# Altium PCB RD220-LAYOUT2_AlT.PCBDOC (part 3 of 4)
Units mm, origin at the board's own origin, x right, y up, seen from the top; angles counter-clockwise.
Board outline 250 x 145 mm, 4 copper layers (TOP, Mid-Layer 1, Mid-Layer 2, BOTTOM), stack 0.711 mm thick; 497 components, 207 nets, 1178 pads, 436 vias.
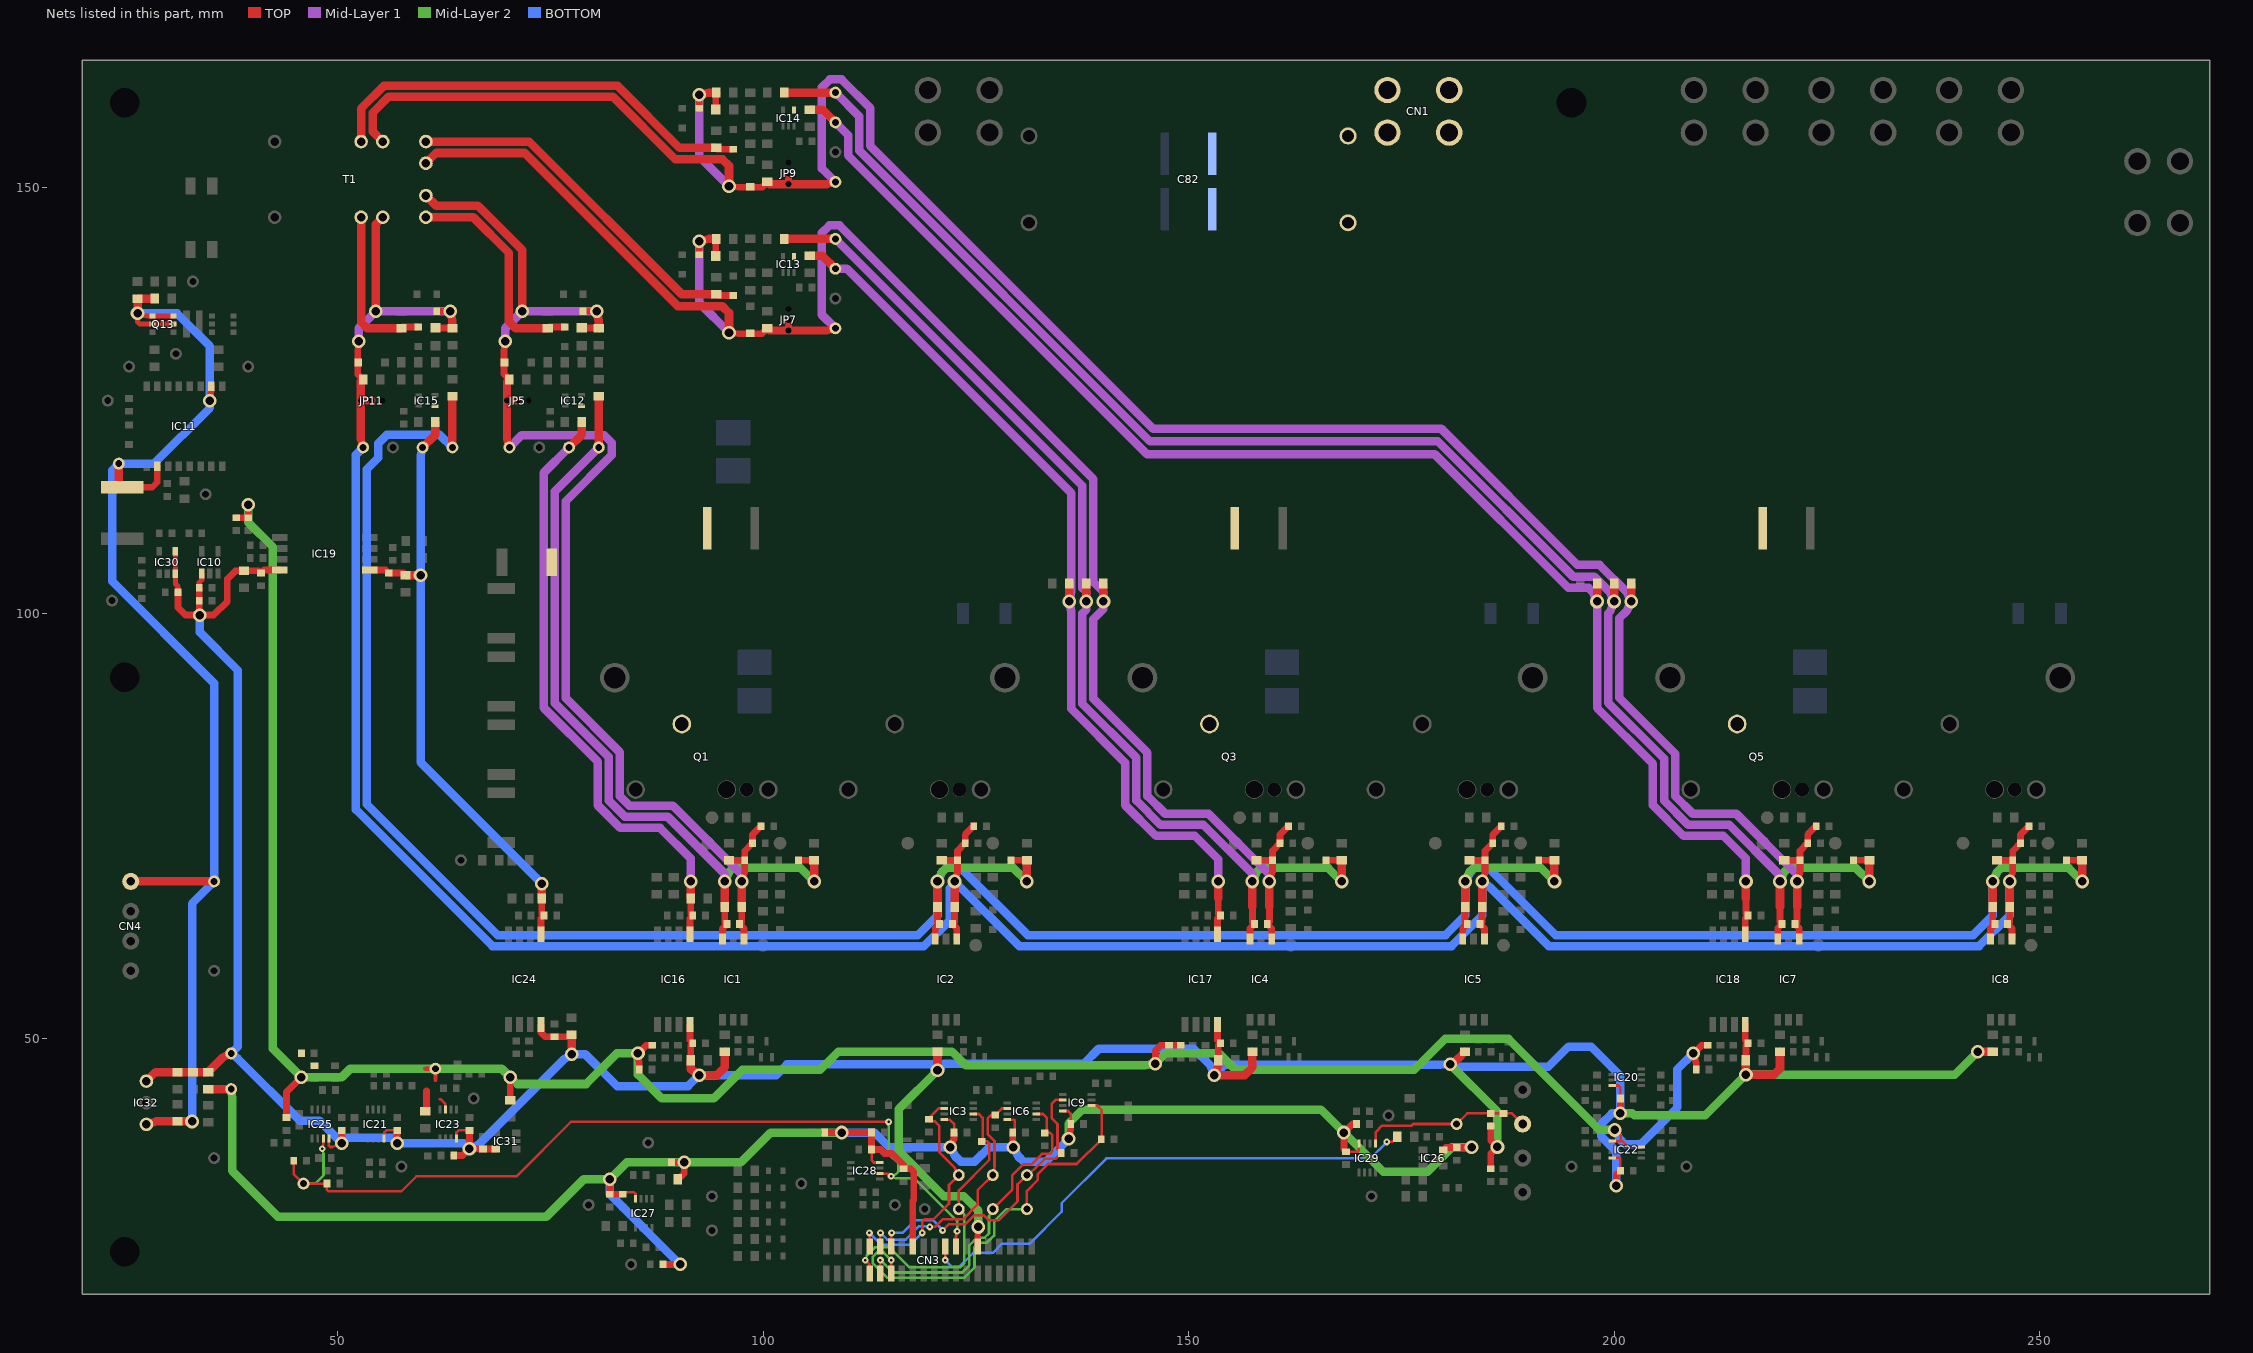
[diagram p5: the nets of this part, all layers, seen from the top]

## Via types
v1: diameter 1.6, hole 1, TOP to BOTTOM, 364 vias
v2: diameter 0.8, hole 0.3, TOP to BOTTOM, 68 vias
v3: diameter 8, hole 3.5, TOP to BOTTOM, 4 vias

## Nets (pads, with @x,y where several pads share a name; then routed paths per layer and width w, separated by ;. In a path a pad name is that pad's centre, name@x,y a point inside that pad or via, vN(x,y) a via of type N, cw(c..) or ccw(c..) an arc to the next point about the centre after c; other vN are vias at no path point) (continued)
T1_B: C68.1 D29.A T1.2 | length 19.4
  TOP w0.8: C68.1@57.5,133.5 57.65,133.65 D29.A@59.5,133.65
  TOP w1: T1.2@52.77,146.555 52.77,134.23 53.5,133.5 C68.1@57.5,133.5
T1_U: C47.1 D16.A T1.4 | length 26.5
  TOP w0.8: C47.1@74.7,133.5 74.85,133.65 D16.A@76.7,133.65
  TOP w1: T1.4@60.4,146.555 65.945,146.555 70.1,142.4 70.1,134.35 70.95,133.5 C47.1@74.7,133.5
T1_V: C54.1 D21.A T1.7 | length 43.6
  TOP w0.8: C54.1@94.5,137.5 94.65,137.35 D21.A@96.5,137.35
  TOP w1: T1.7@60.39,155.445 72.505,155.445 90.45,137.5 C54.1@94.5,137.5
T1_W: C61.1 D25.A T1.9 | length 51.8
  TOP w0.8: C61.1@94.5,154.7 94.65,154.55 D25.A@96.5,154.55
  TOP w1: T1.9@52.77,155.45 52.77,159.32 55.45,162 82.9,162 90.2,154.7 C61.1@94.5,154.7
T_RES: C117.2 IC29.5 J3.1 R117.2 TP60.1 | length 20
  TOP w0.3: IC29.5@171.975,37.7 171.975,39.025 172.75,39.8 176.2,39.8 176.4,40 TP60.1@181.5,40 182.75,41.25 R117.2@185.5,41.25 C117.2@187,41.25 188,41.25 J3.1@189.25,40
THM1: CN3.24 R116.2 | length 61.9
  TOP w0.3: v2(121.405,24.006) CN3.24@121.405,25.531 ; v2(173.3,37.9) 173.9,37.9 R116.2@174.5,38.5
  BOTTOM w0.3: v2(121.405,24.006) 122.211,23.2 123.05,23.2 124.7,24.85 127,24.85 128.1,25.95 131.35,25.95 135.1,29.7 135.1,30.7 140.35,35.95 171.35,35.95 v2(173.3,37.9)
UH: CN3.9 IC3.2 R162.1 TP62.1 | length 36.3
  TOP w0.3: v2(112,24) 112.515,23.485 CN3.9@112.515,22.481 ; TP62.1@123,30 123,32.2 126.6,35.8 126.6,37.7 126.35,37.95 R162.1@125.7,37.95 125.8,38.05 125.8,40.725 125.35,41.175 IC3.2@124.7,41.175
  Mid-Layer 2 w0.3: v2(112,24) 112.211,24.561 113.15,25.5 114.85,25.5 117.2,23.15 123.15,23.15 123.65,23.65 123.65,29.35 TP62.1@123,30
UL: CN3.10 IC3.6 R163.1 TP65.1 | length 28.9
  TOP w0.3: v2(112.5,27.2) 112.515,26.675 CN3.10@112.515,25.601 CN3.10@112.515,25.531 ; v2(118.7,27.2) 118.7,28.5 119,28.8 120,28.8 121.85,30.65 121.85,32.85 TP65.1@123,34 122.475,34.91 120.7,36.685 120.7,39.8 120.2,40.3 119.5,40.3 R163.1@119.5,40.55 119.5,40.7 120.625,41.825 IC3.6@121.3,41.825
  BOTTOM w0.3: v2(112.5,27.2) 113.9,25.8 117.3,25.8 v2(118.7,27.2)
VDC: C164.2 CN3.26 IC25.7 IC28.6 R157.1 TP56.1 | length 105
  TOP w0.3: C164.2@44.85,35.7 44.85,34.15 TP56.1@46,33 R157.1@48.75,33 48.75,32.275 48.925,32.1 57.5,32.1 59.25,33.85 71.004,33.85 77.404,40.25 v2(114.75,40.25) ; v2(48.2,37.1) 48.325,37.61 IC25.7@48.325,38.3 ; IC28.6@113.7,34.175 114.725,34.175 v2(115.05,33.85) ; CN3.26@122.675,25.531 CN3.26@122.675,25.601 122.675,26.89 v2(122.8,27.4)
  Mid-Layer 2 w0.3: TP56.1@46,33 47.4,33 48.35,33.95 48.35,36.519 v2(48.2,37.1) ; v2(114.75,40.25) 114.75,36.5 115.9,35.35 115.9,34.4 115.597,34.097 v2(115.05,33.85) 115.595,33.6 117.804,33.6 122.8,28.604 v2(122.8,27.4)
VDD5_A: C39.2 C78.2 C79.2 C98.2 C99.2 C103.2 C104.2 C108.2 C109.2 C113.2 C114.2 C119.2 C120.2 C121.2 C122.2 C123.2 C128.2 C148.2 C150.2 CN3.30 IC10.1 IC16.8 IC17.8 IC18.8 IC19.8 IC20.8 IC21.8 IC22.8 IC23.8 IC24.8 IC25.8 IC30.3 IC30.4 IC31.5 IC32.3 R13.2 R16.2 R30.2 R33.2 R38.2 R41.2 R46.2 R111.1 R117.1 R121.1 R186.1 R187.2 TP70.1 | length 457.3
  TOP w0.3: IC25.8@48.975,38.3 48.975,37.475 49.15,37.3 49.388,37.3 v1(50.5,37.75) ; IC21.8@55.475,38.3 55.475,38.975 55.75,39.25 C122.2@57,39.25 ; IC23.8@63.975,38.3 63.975,39 64.225,39.25 C123.2@65.5,39.25 ; IC22.8@199.8,36.025 200.65,36.025 200.75,35.925 C121.2@200.75,34.5 ; IC20.8@199.8,44.525 200.525,44.525 200.75,44.3 C120.2@200.75,43
  TOP w0.6: IC30.4@30.95,107.315 IC30.3@30.95,104.685 30.95,103.45 31.25,103.15 C128.2@31.25,102.5 ; C39.2@33.75,103 33.75,103.65 34.05,103.95 IC10.1@34.05,104.69
  TOP w0.7: CN3.30@125.215,25.531 CN3.30@125.215,25.601 125.215,26.727 125.315,27.899 v1@125.315,27.9
  TOP w0.8: C128.2@31.25,102.5 31.25,100.7 32.15,99.8 v1(33.8,99.8) ; C39.2@33.75,103 R46.2@33.75,101.5 33.75,100.999 v1(33.8,99.8) ; IC19.8@43.2,105.095 41.345,105.095 C99.2@41,104.75 40.75,105 C98.2@39,105 38,105 37.05,104.05 37.05,101.4 35.45,99.8 v1(33.8,99.8) ; v1(50.5,37.75) C119.2@50.5,39.25 ; v1(57,37.75) C122.2@57,39.25 ; R121.1@63.65,36.3 64.7,36.3 v1(65.5,37.1) ; C123.2@65.5,39.25 v1(65.5,37.1) ; IC31.5@68.6,37.05 C148.2@67.1,37.05 66.699,37.05 v1(65.5,37.1) ; IC24.8@73.905,51.7 73.905,50.77 74.425,50.25 C79.2@75.5,50.25 77.25,50.25 C78.2@77.5,50.5 ; IC16.8@91.405,51.7 91.405,49.845 C104.2@91.75,49.5 91.5,49.25 C103.2@91.5,47.5 ; IC17.8@153.405,51.7 153.405,49.845 C109.2@153.75,49.5 153.5,49.25 C108.2@153.5,47.5 ; R111.1@185.5,34.75 185.5,36.5 v1(186.3,37.3) 185.5,38.1 R117.1@185.5,39.75 ; v1(200.25,32.75) 200.25,34 C121.2@200.75,34.5 ; v1(200.75,41.25) C120.2@200.75,43 ; IC18.8@215.405,51.7 215.405,49.845 C114.2@215.75,49.5 215.5,49.25 C113.2@215.5,47.5
  TOP w1: IC32.3@27.55,45.04 28.61,46.1 C150.2@31.2,46.1 R186.1@33,46.1 R187.2@34.8,46.1 36.551,47.851 TP70.1@37.5,48.3 ; v1@77.5,48 v1(77.5,48.2) C78.2@77.5,50.5 ; C103.2@91.5,47.5 91.5,46.45 91.515,46.435 v1(92.5,45.75) 94.6,45.75 95.5,46.65 R13.2@95.5,48.5 ; v1(120.5,46.3) R16.2@120.5,48.5 ; C108.2@153.5,47.5 153.5,46.841 v1(153,45.75) 156.6,45.75 157.5,46.65 R30.2@157.5,48.5 ; v1(180.75,47) 181.714,47.714 R33.2@182.5,48.5 ; C113.2@215.5,47.5 v1(215.5,45.8) 218.8,45.8 219.5,46.5 R38.2@219.5,48.5 ; v1(242.75,48.5) R41.2@244.5,48.5
  Mid-Layer 2 w1: v1(120.5,46.3) 115.95,41.75 115.95,36.8 121.25,31.5 123.6,31.5 125.3,29.8 v1(125.3,27.9) ; v1(180.75,47) 186.3,41.45 v1(186.3,37.3) ; v1(200.75,41.25) 202.15,41.25 202.4,41 210.7,41 v1(215.5,45.8) 240.05,45.8 v1(242.75,48.5)
  BOTTOM w1: v1(33.8,99.8) 33.8,97.8 38.3,93.3 38.3,49.1 TP70.1@37.5,48.3 38.314,47.636 45.55,40.4 47.85,40.4 v1(50.5,37.75) 51.15,38.4 56.35,38.4 v1(57,37.75) 64.85,37.75 v1(65.5,37.1) 66.594,37.594 76.515,47.515 v1(77.5,48.2) 79.1,48.2 82.85,44.45 91.2,44.45 v1(92.5,45.75) 101.55,45.75 102.8,47 119.8,47 v1(120.5,46.3) 121.3,47.1 137.7,47.1 139.45,48.85 150.6,48.85 152.577,46.873 v1(153,45.75) 154.2,46.95 179.551,46.95 v1(180.75,47) 181.912,46.7 192.25,46.7 194.65,49.1 197.3,49.1 200.75,45.65 v1(200.75,41.25) 199.75,41.25 198.5,40 198.5,38.55 200.25,36.8 v1(200.25,32.75)
VDD5_D: C88.2 C89.2 C90.2 C116.2 C124.2 C125.2 C126.2 CN3.18 IC3.8 IC6.8 IC9.8 IC26.5 IC27.8 IC28.8 IC29.8 R86.1 R88.1 R90.1 R94.1 R95.1 R97.1 R99.1 R100.1 R187.1 TP72.1 | length 247.4
  TOP w0.3: C88.2@83.6,32 84.8,32 85.025,31.775 IC27.8@85.025,31.2 ; C89.2@112.75,37 112.75,35.75 113.025,35.475 IC28.8@113.7,35.475 ; IC3.8@121.3,40.525 121.925,40.525 122.45,40 C124.2@122.45,39 ; IC6.8@128.7,40.525 129.475,40.525 129.6,40.4 129.6,39.25 C125.2@129.35,39 ; IC9.8@135.2,41.525 135.85,41.525 136.15,41.225 C126.2@136.15,40 ; C90.2@168.5,36.75 169.9,36.75 170.025,36.875 IC29.8@170.025,37.7
  TOP w0.8: v1(82,33.5) R99.1@82,31.75 C88.2@83.5,31.75 ; R86.1@88.25,23.5 v1(90.25,23.5) ; R88.1@89.25,35.5 v1(90.75,35.5) 90.75,34.25 R94.1@90,33.5 ; R90.1@107.25,39 v1(109.25,39) R100.1@112.75,39 C89.2@112.75,37 113.8,37 114.25,36.55 115.15,36.55 116.5,35.2 R95.1@116.5,34.75 117.35,34.75 117.7,34.4 117.7,31.05 117.6,30.95 CN3.18@117.6,25.536 ; v1(122,37.25) 122.45,38.362 C124.2@122.45,39 ; C125.2@129.35,39 129.35,38.449 v1(129.4,37.25) ; v1(135.9,38.25) 136.15,39.424 C126.2@136.15,40 ; C90.2@168.5,36.75 168.25,37 v1(168.25,39) 169.25,40 R97.1@169.75,40 ; IC26.5@179.95,36.95 180.25,37.25 C116.2@181.5,37.25 v1(183.25,37.25)
  TOP w1: R187.1@34.8,44.1 TP72.1@37.5,44.1
  Mid-Layer 2 w1: TP72.1@37.5,44.1 37.6,43.13 37.6,34.5 43,29.1 74.525,29.1 78.925,33.5 v1(82,33.5) 84,35.5 v1(90.75,35.5) 97.4,35.5 100.9,39 v1(109.25,39) ; v1(135.9,38.25) 135.9,40.05 137.55,41.7 165.55,41.7 v1(168.25,39) 172.85,34.4 178.1,34.4 180.95,37.25 v1(183.25,37.25)
  BOTTOM w1: v1(82,33.5) 82,31.75 v1(90.25,23.5) ; v1(109.25,39) 113.1,39 114.85,37.25 v1(122,37.25) 122.593,36.207 123.225,35.575 124.875,35.575 126.55,37.25 v1(129.4,37.25) 129.993,36.207 130.65,35.55 133.2,35.55 v1(135.9,38.25)
VDD20_A: C43.2 C44.2 C45.2 C149.2 CN4.1 IC11.2 IC11.10 IC32.1 Q13.1 Q13.2 Q13.5 Q13.6 TP27.1 TP69.1 | length 153.9
  TOP w0.6: Q13.5@30.75,134 Q13.2@28.25,134 26.775,134 26.5,134.275 v1(26.5,135.25) 27.662,134.95 Q13.1@28.25,134.95 Q13.6@30.75,134.95
  TOP w0.75: C43.2@24.7,114.825 24.708,114.817 28.217,114.817 28.825,115.425 IC11.2@28.825,117.301 ; v1(35,125) 35.175,126.187 IC11.10@35.175,126.699
  TOP w1: TP27.1@24.3,117.6 24.3,115.225 C43.2@24.7,114.825 ; CN4.1@25.7,68.5 TP69.1@35.5,68.5 ; v1(26.5,135.25) C44.2@26.5,137 C45.2@28.5,137 ; IC32.1@27.55,39.96 28.701,40.3 C149.2@31.2,40.3 v1(32.9,40.3)
  BOTTOM w1: v1(26.5,135.25) 31.15,135.25 35,131.4 v1(35,125) 35,124.15 28.45,117.6 TP27.1@24.3,117.6 23.5,116.8 23.5,103.8 35.5,91.8 TP69.1@35.5,68.5 32.9,65.9 v1(32.9,40.3)
VH: CN3.11 IC6.2 R170.1 TP63.1 | length 38.2
  TOP w0.3: CN3.11@113.785,22.481 v2(113.785,24.006) ; TP63.1@127,30 129.3,32.3 129.3,34 130.55,35.25 131.525,35.25 132.775,36.5 133.7,36.5 134,36.8 134,38.7 133.75,38.95 R170.1@133.1,38.95 133.35,39.2 133.35,40.7 132.875,41.175 IC6.2@132.1,41.175
  Mid-Layer 2 w0.3: v2(113.785,24.006) 115.241,22.55 123.4,22.55 124.25,23.4 124.25,25.75 125.15,26.65 126.05,26.65 126.55,27.15 126.55,29.135 TP63.1@127,30
VL: CN3.12 IC6.6 R171.1 TP66.1 | length 29.2
  TOP w0.3: CN3.12@113.785,25.531 CN3.12@113.785,25.601 113.785,26.675 v2(113.8,27.2) ; v2(119.6,27.9) 120.2,27.9 121.1,28.8 123.5,28.8 125.215,30.515 125.215,32.215 TP66.1@127,34 127.2,35.031 127.2,38 126.4,38.8 126.4,40.65 126.8,41.05 R171.1@127.3,41.05 128.075,41.825 IC6.6@128.7,41.825
  BOTTOM w0.3: v2(113.8,27.2) 114.6,26.4 116.75,26.4 118.35,28 119.085,28 v2(119.6,27.9)
VN_2V_B: C24.1 C26.1 C30.1 C32.1 C36.1 C38.1 C69.1 C74.1 C130.1 C132.1 C134.1 C138.1 C143.1 C147.1 D4.A D8.A D12.A D28.A DS4.C IC2.4 IC5.4 IC8.4 JP11.1 JP11.2 R26.2 R37.2 R45.2 T1.3 TP44.1 ZD4.A | length 359.6
  TOP w0.8: v1(52.5,132) 52.365,130.808 52.365,128.135 C74.1@53,127.5 ; DS4.C@61.5,133.55 63.45,133.55 C69.1@63.5,133.5 ; D28.A@61.65,135.5 v1(63.25,135.5) ; C26.1@121,71 D4.A@122.85,71 ; C130.1@122.5,65.5 122.5,63.75 C24.1@122.25,63.5 122.77,62.98 IC2.4@122.77,61.75 ; v1(122.5,68.5) 122.85,69.648 D4.A@122.85,71 ; C138.1@124.75,75 123.75,74 R26.2@123.75,73 122.85,72.1 D4.A@122.85,71 ; C32.1@183,71 D8.A@184.85,71 ; C132.1@184.5,65.5 184.5,63.75 C30.1@184.25,63.5 184.77,62.98 IC5.4@184.77,61.75 ; v1(184.5,68.5) 184.85,69.648 D8.A@184.85,71 ; C143.1@186.75,75 185.75,74 R37.2@185.75,73 184.85,72.1 D8.A@184.85,71 ; C38.1@245,71 D12.A@246.85,71 ; C134.1@246.5,65.5 246.5,63.75 C36.1@246.25,63.5 246.77,62.98 IC8.4@246.77,61.75 ; v1(246.5,68.5) 246.85,69.648 D12.A@246.85,71 ; C147.1@248.75,75 247.75,74 R45.2@247.75,73 246.85,72.1 D12.A@246.85,71
  TOP w0.95: TP44.1@53,119.5 52.73,120.515 JP11.1@52.73,125 ; C74.1@53,127.5 52.73,127.23 JP11.1@52.73,125 ; JP11.2@54,125 JP11.1@52.73,125
  TOP w1: v1(54.5,135.5) 54.5,145.745 T1.3@55.31,146.555 ; v1(63.25,135.5) 63.5,134.326 C69.1@63.5,133.5 ; C130.1@122.5,65.5 v1(122.5,68.5) ; C132.1@184.5,65.5 v1(184.5,68.5) ; C134.1@246.5,65.5 v1(246.5,68.5)
  Mid-Layer 1 w1: v1(52.5,132) 52.5,133.5 v1(54.5,135.5) v1(63.25,135.5)
  BOTTOM w1: TP44.1@53,119.5 52.15,118.65 52.15,76.95 68.2,60.9 118.9,60.9 121.95,63.95 121.95,67.7 v1(122.5,68.5) 130.1,60.9 180.9,60.9 184.5,64.5 v1(184.5,68.5) 185.454,67.771 192.325,60.9 242.9,60.9 246.5,64.5 v1(246.5,68.5)
VN_2V_U: C21.1 C23.1 C48.1 C53.1 C129.1 C137.1 D2.A D15.A DS1.C IC1.4 JP5.1 JP5.2 R25.2 T1.5 TP32.1 ZD1.A | length 148.6
  TOP w0.8: v1(69.7,132) 69.565,130.808 69.565,128.135 C53.1@70.2,127.5 ; DS1.C@78.7,133.55 80.65,133.55 C48.1@80.7,133.5 ; D15.A@78.85,135.5 v1(80.45,135.5) ; C23.1@96,71 D2.A@97.85,71 ; C129.1@97.5,65.5 97.5,63.75 C21.1@97.25,63.5 97.77,62.98 IC1.4@97.77,61.75 ; v1(97.5,68.5) 97.85,69.648 D2.A@97.85,71 ; C137.1@99.75,75 98.75,74 R25.2@98.75,73 97.85,72.1 D2.A@97.85,71
  TOP w0.95: TP32.1@70.2,119.5 69.93,120.515 JP5.1@69.93,125 ; C53.1@70.2,127.5 69.93,127.23 JP5.1@69.93,125 ; JP5.2@71.2,125 JP5.1@69.93,125
  TOP w1: T1.5@60.4,149.1 61.6,147.9 66.5,147.9 71.7,142.7 v1(71.7,135.5) ; v1(80.45,135.5) 80.7,134.326 C48.1@80.7,133.5 ; C129.1@97.5,65.5 v1(97.5,68.5)
  Mid-Layer 1 w1: v1(69.7,132) 69.7,133.5 v1(71.7,135.5) v1(80.45,135.5) ; TP32.1@70.2,119.5 71.65,120.95 81.325,120.95 82.2,120.075 82.2,118.575 76.83,113.205 76.83,90.02 83.17,83.68 83.17,78.534 84.304,77.4 89.4,77.4 97.5,69.3 v1(97.5,68.5)
VN_2V_V: C27.1 C29.1 C55.1 C60.1 C131.1 C141.1 D6.A D20.A DS2.C IC4.4 JP7.2 JP7.3 R36.2 T1.6 TP36.1 ZD2.A | length 212.9
  TOP w0.8: D20.A@92.5,142.15 v1(92.5,143.75) ; DS2.C@94.45,142 94.45,143.95 C55.1@94.5,144 ; v1(96,133) 97.192,132.865 99.865,132.865 C60.1@100.5,133.5 ; JP7.3@103,133.23 JP7.2@103,134.5 ; C29.1@158,71 D6.A@159.85,71 ; 159.5,65.5 159.5,63.75 C27.1@159.25,63.5 159.77,62.98 IC4.4@159.77,61.75 ; v1(159.5,68.5) 159.85,69.648 D6.A@159.85,71 ; C141.1@161.75,75 160.75,74 R36.2@160.75,73 159.85,72.1 D6.A@159.85,71
  TOP w0.95: C60.1@100.5,133.5 100.77,133.23 JP7.3@103,133.23 107.485,133.23 TP36.1@108.5,133.5
  TOP w1: T1.6@60.39,152.905 61.585,154.1 72,154.1 90,136.1 95.2,136.1 96,135.3 v1(96,133) ; v1(92.5,143.75) 93.674,144 C55.1@94.5,144 ; v1(140,101.4) C131.1@140,103.5 ; 159.5,65.5 v1(159.5,68.5)
  Mid-Layer 1 w1: v1(92.5,143.75) 92.5,136.5 v1(96,133) ; TP36.1@108.5,133.5 106.9,135.1 106.9,144.7 107.8,145.6 109,145.6 138.83,115.77 138.83,103.67 140,102.5 v1(140,101.4) 140,100.5 138.83,99.33 138.83,89.97 145.17,83.63 145.17,78.534 147.254,76.45 152.35,76.45 159.5,69.3 v1(159.5,68.5)
VN_2V_W: C33.1 C35.1 C62.1 C67.1 C133.1 C145.1 D10.A D24.A DS3.C IC7.4 JP9.2 JP9.3 R44.2 T1.8 TP40.1 ZD3.A | length 283.2
  TOP w0.8: D24.A@92.5,159.35 v1(92.5,160.95) ; DS3.C@94.45,159.2 94.45,161.15 C62.1@94.5,161.2 ; v1(96,150.2) 97.192,150.065 99.865,150.065 C67.1@100.5,150.7 ; JP9.3@103,150.43 JP9.2@103,151.7 ; C35.1@220,71 D10.A@221.85,71 ; 221.5,65.5 221.5,63.75 C33.1@221.25,63.5 221.77,62.98 IC7.4@221.77,61.75 ; v1(221.5,68.5) 221.85,69.648 D10.A@221.85,71 ; C145.1@223.75,75 222.75,74 R44.2@222.75,73 221.85,72.1 D10.A@221.85,71
  TOP w0.95: C67.1@100.5,150.7 100.77,150.43 JP9.3@103,150.43 107.485,150.43 TP40.1@108.5,150.7
  TOP w1: T1.8@55.3,155.45 54.15,156.6 54.15,158.85 56,160.7 82.35,160.7 89.7,153.35 95.25,153.35 96,152.6 v1(96,150.2) ; v1(92.5,160.95) 93.674,161.2 C62.1@94.5,161.2 ; v1(202,101.4) C133.1@202,103.5 ; 221.5,65.5 v1(221.5,68.5)
  Mid-Layer 1 w1: v1(92.5,160.95) 92.5,153.7 v1(96,150.2) ; TP40.1@108.5,150.7 106.925,152.275 106.925,161.825 107.85,162.75 109.225,162.75 112.6,159.375 112.6,154.925 145.825,121.7 179.7,121.7 195.7,105.7 198.3,105.7 201.506,102.494 v1(202,101.4) 201.506,100.306 200.6,99.4 200.6,90.1 207.17,83.53 207.17,78.534 209.254,76.45 214.35,76.45 221.5,69.3 v1(221.5,68.5)
VP_5V_B: C72.2 C76.2 C77.2 C96.2 C97.2 IC15.4 IC19.1 IC24.1 TP42.1 | length 73.2
  TOP w0.8: IC19.1@53.8,105.095 55.655,105.095 C97.2@56,104.75 57.75,104.75 C96.2@58,104.5 ; IC24.1@73.905,62.3 73.905,64.155 C77.2@74.25,64.5 74,64.75 C76.2@74,66.5
  TOP w1: C96.2@58,104.5 v1(59.75,104.5) ; TP42.1@60,119.5 61.5,121 C72.2@61.5,122.5 ; C76.2@74,66.5 v1(74,68.25)
  BOTTOM w1: TP42.1@60,119.5 59.75,118.48 v1(59.75,104.5) 59.75,82.5 v1(74,68.25)
VP_5V_U: C51.2 C101.2 C102.2 IC12.4 IC16.1 TP30.1 | length 72.2
  TOP w0.8: IC16.1@91.405,62.3 91.405,64.155 C102.2@91.75,64.5 91.5,64.75 C101.2@91.5,66.5
  TOP w1: TP30.1@77.2,119.5 78.7,121 C51.2@78.7,122.5 ; C101.2@91.5,66.5 v1(91.5,68.5)
  Mid-Layer 1 w1: TP30.1@77.2,119.5 74.23,116.53 74.23,88.92 80.57,82.58 80.57,77.457 83.227,74.8 87.9,74.8 91.5,71.2 v1(91.5,68.5)
VP_5V_V: C58.2 C106.2 C107.2 IC13.4 IC17.1 TP34.1 | length 106.3
  TOP w0.8: IC17.1@153.405,62.3 153.405,64.155 C107.2@153.75,64.5 153.5,64.75 153.5,66.5
  TOP w1: C58.2@105.5,142 107,142 TP34.1@108.5,140.5 ; v1(136,101.4) C106.2@136,103.5 ; 153.5,66.5 v1(153.5,68.5)
  Mid-Layer 1 w1: TP34.1@108.5,140.5 109.85,140.5 136.23,114.12 136.23,102.578 v1(136,101.4) 136.23,100.222 136.23,88.77 142.57,82.43 142.57,77.457 146.177,73.85 150.75,73.85 153.5,71.1 v1(153.5,68.5)
VP_5V_W: C65.2 C111.2 C112.2 IC14.4 IC18.1 TP38.1 | length 169.5
  TOP w0.8: IC18.1@215.405,62.3 215.405,64.155 C112.2@215.75,64.5 215.5,64.75 215.5,66.5
  TOP w1: C65.2@105.5,159.2 107,159.2 TP38.1@108.5,157.7 ; v1(198,101.4) C111.2@198,103.5 ; 215.5,66.5 v1(215.5,68.5)
  Mid-Layer 1 w1: TP38.1@108.5,157.7 110,156.2 110,153.825 145.125,118.7 178.939,118.7 194.639,103 197,103 197.506,102.494 v1(198,101.4) 198,88.9 204.57,82.33 204.57,77.457 208.177,73.85 212.85,73.85 215.5,71.2 v1(215.5,68.5)
VP_18V_B: C24.2 C25.2 C30.2 C31.2 C36.2 C37.2 C130.2 C132.2 C134.2 D3.C D7.C D11.C IC2.6 IC5.6 IC8.6 R61.2 TP41.1 | length 349.8
  TOP w0.8: IC2.6@120.23,61.75 120.23,62.98 C24.2@120.75,63.5 120.5,63.75 C130.2@120.5,65.5 ; D3.C@129.15,71 C25.2@131,71 ; IC5.6@182.23,61.75 182.23,62.98 C30.2@182.75,63.5 182.5,63.75 C132.2@182.5,65.5 ; D7.C@191.15,71 C31.2@193,71 ; IC8.6@244.23,61.75 244.23,62.98 C36.2@244.75,63.5 244.5,63.75 C134.2@244.5,65.5 ; D11.C@253.15,71 C37.2@255,71
  TOP w1: TP41.1@63.5,119.5 R61.2@63.5,125.5 ; C130.2@120.5,65.5 v1(120.5,68.5) ; v1(131,68.5) C25.2@131,71 ; C132.2@182.5,65.5 v1(182.5,68.5) ; v1(193,68.5) C31.2@193,71 ; C134.2@244.5,65.5 v1(244.5,68.5) ; v1(255,68.5) C37.2@255,71
  Mid-Layer 2 w1: v1(120.5,68.5) 120.994,69.594 121.5,70.1 129.4,70.1 v1(131,68.5) ; v1(182.5,68.5) 182.994,69.594 183.5,70.1 191.4,70.1 v1(193,68.5) ; v1(244.5,68.5) 244.994,69.594 245.5,70.1 253.4,70.1 v1(255,68.5)
  BOTTOM w1: TP41.1@63.5,119.5 62,121 55.8,121 54.8,120 54.8,118.3 53.45,116.95 53.45,77.55 68.8,62.2 118.2,62.2 120.5,64.5 v1(120.5,68.5) 121.028,69.578 121.55,70.1 123.2,70.1 131.1,62.2 180.2,62.2 182.5,64.5 v1(182.5,68.5) 183.093,69.543 183.675,70.125 185.2,70.125 193.125,62.2 242.2,62.2 244.5,64.5 v1(244.5,68.5)
VP_18V_U: C21.2 C22.2 C129.2 D1.C IC1.6 R52.2 TP29.1 | length 93.9
  TOP w0.8: IC1.6@95.23,61.75 95.23,62.98 C21.2@95.75,63.5 95.5,63.75 C129.2@95.5,65.5 ; D1.C@104.15,71 C22.2@106,71
  TOP w1: TP29.1@80.7,119.5 R52.2@80.7,125.5 ; C129.2@95.5,65.5 v1(95.5,68.5) ; v1(106,68.5) C22.2@106,71
  Mid-Layer 1 w1: TP29.1@80.7,119.5 75.53,114.33 75.53,89.47 81.87,83.13 81.87,77.995 83.765,76.1 88.8,76.1 95.5,69.4 v1(95.5,68.5)
  Mid-Layer 2 w1: v1(95.5,68.5) 95.994,69.594 96.5,70.1 104.4,70.1 v1(106,68.5)
VP_18V_V: C27.2 C28.2 C131.2 D5.C IC4.6 R55.2 TP33.1 | length 130.7
  TOP w0.8: IC4.6@157.23,61.75 157.23,62.98 C27.2@157.75,63.5 157.5,63.75 157.5,65.5 ; D5.C@166.15,71 C28.2@168,71
  TOP w1: R55.2@102.5,144 TP33.1@108.5,144 ; v1(138,101.4) C131.2@138,103.5 ; 157.5,65.5 v1(157.5,68.5) ; v1(168,68.5) C28.2@168,71
  Mid-Layer 1 w1: TP33.1@108.5,144 137.53,114.97 137.53,102.97 138,102.5 v1(138,101.4) 138,100.47 137.53,100 137.53,89.37 143.87,83.03 143.87,77.995 146.715,75.15 151.75,75.15 157.5,69.4 v1(157.5,68.5)
  Mid-Layer 2 w1: v1(157.5,68.5) 157.994,69.594 158.5,70.1 166.4,70.1 v1(168,68.5)
VP_18V_W: C33.2 C34.2 C133.2 D9.C IC7.6 R58.2 TP37.1 | length 194.7
  TOP w0.8: IC7.6@219.23,61.75 219.23,62.98 C33.2@219.75,63.5 219.5,63.75 219.5,65.5 ; D9.C@228.15,71 C34.2@230,71
  TOP w1: R58.2@102.5,161.2 TP37.1@108.5,161.2 ; v1(200,101.4) C133.2@200,103.5 ; 219.5,65.5 v1(219.5,68.5) ; v1(230,68.5) C34.2@230,71
  Mid-Layer 1 w1: TP37.1@108.5,161.2 111.3,158.4 111.3,154.375 145.475,120.2 179.3,120.2 195.2,104.3 197.7,104.3 199.506,102.494 v1(200,101.4) 199.577,100.277 199.3,100 199.3,89.5 205.87,82.93 205.87,77.995 208.715,75.15 213.55,75.15 219.3,69.4 v1(219.5,68.5)
  Mid-Layer 2 w1: v1(219.5,68.5) 219.994,69.594 220.5,70.1 228.4,70.1 v1(230,68.5)
VP_DC: C82.1 C82.2 C84.2 C85.2 C86.2 C87.2 C127.2 CN1.1 CN1.2 CN1.3 CN1.4 Q1.2 Q3.2 Q5.2 R66.1
VREF_2.5V: C153.1 C154.1 C159.1 C160.1 C163.1 IC22.3 IC22.5 IC23.3 R126.2 R132.2 R140.2 R146.2 R151.2 R152.2 R189.2 R190.2 TP45.1 | length 293.6
  TOP w0.3: 62.016,42.9 62.15,42.9 62.675,42.375 IC23.3@62.675,41.7 ; IC22.5@199.8,37.975 200.8,37.975 ; v1(200.1,39.3) 200.8,38.6 200.8,37.975 ; IC22.3@203.2,37.325 201.625,37.325 200.975,37.975 200.8,37.975
  TOP w0.5: 60.3,46.5 TP45.1@61.5,46.5 61.5,45.2
  TOP w0.8: C160.1@38.1,111.25 R146.2@39.5,111.25 v1(39.5,112.75) ; R152.2@44,40.75 44,43.75 v1(45.75,45.5) ; R189.2@60.3,41.5 60.45,41.65 60.45,43.898 ; R190.2@70.3,42.8 v1(70.3,45.5) ; C159.1@85.45,46.4 85.45,47.109 v1(85.3,48.3) 86.25,49.25 R140.2@87,49.25 ; v1(146.1,47.1) 146.1,48.65 146.7,49.25 C154.1@147.7,49.25 R132.2@149.1,49.25 ; C153.1@209.65,46.4 209.65,47.152 v1(209.3,48.3) 210.25,49.25 R126.2@211,49.25
  Mid-Layer 2 w1: v1(39.5,112.75) 39.5,110.7 42.4,107.8 42.4,48.85 v1(45.75,45.5) 50.5,45.5 51.5,46.5 TP45.1@61.5,46.5 69.3,46.5 v1(70.3,45.5) 71.1,44.7 79.2,44.7 82.8,48.3 v1(85.3,48.3) 85.3,45.8 88.1,43 94.2,43 97.55,46.35 106.7,46.35 108.85,48.5 122.2,48.5 123.8,46.9 144.917,46.9 v1(146.1,47.1) 147.3,48.3 153.6,48.3 155.55,46.35 176.5,46.35 180.15,50 187.6,50 198.3,39.3 v1(200.1,39.3)
  BOTTOM w1: v1(200.1,39.3) 200.661,38.239 201.3,37.6 203.1,37.6 207.45,41.95 207.45,46.45 v1(209.3,48.3)
WH: CN3.13 IC9.2 R178.1 TP64.1 | length 48.2
  TOP w0.3: CN3.13@115.055,22.481 v2(115.055,24.006) ; TP64.1@131,30 131,32.15 132.3,33.45 132.3,34.1 133.5,35.3 136.85,35.3 R178.1@139.75,38.2 139.8,38.25 139.8,41.625 139.25,42.175 IC9.2@138.6,42.175
  Mid-Layer 2 w0.3: v2(115.055,24.006) 114.161,24.9 113.4,24.9 112.9,24.4 112.9,23.621 114.571,21.95 123.65,21.95 124.85,23.15 124.85,25.5 125.4,26.05 126.3,26.05 127.15,26.9 127.15,28.55 128.6,30 TP64.1@131,30
WL: CN3.14 IC9.6 R179.1 TP67.1 | length 35.8
  TOP w0.3: CN3.14@115.055,25.531 CN3.14@115.055,25.601 115.055,26.677 v2(115.1,27.2) ; v2(121.1,27.5) 121.8,28.2 123.75,28.2 124.85,29.3 125.9,29.3 126.5,28.7 127.7,28.7 129.9,30.9 129.9,32.9 TP67.1@131,34 131.836,34.636 133.1,35.9 134.35,35.9 R179.1@135.05,36.6 134.6,37.05 134.6,40 133.95,40.65 133.95,42.4 134.375,42.825 IC9.6@135.2,42.825
  BOTTOM w0.3: v2(115.1,27.2) 116.4,27.2 117.9,28.7 119.95,28.7 120.755,27.895 v2(121.1,27.5)
pads on no net: CN3.3 CN3.4 CN3.5 CN3.6 CN3.7 CN3.8 CN3.17 CN3.20 CN3.21 CN3.22 CN3.23 CN3.27 CN3.28 CN3.32 CN3.34 CN4.2 CN4.3 HS1.2 HS2.2 HS3.2 IC1.2 IC2.2 IC4.2 IC5.2 IC7.2 IC8.2 IC10.4

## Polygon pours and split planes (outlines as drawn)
no net on Bottom Overlay "BOTTOMOVERLAY296" (solid, pour order 0): 69.15,123.9 cw(c69.15,123.95) 69.1,123.95 69.1,126.05 cw(c69.15,126.05) 69.15,126.1 73.25,126.1 cw(c73.25,126.05) 73.3,126.05 73.3,123.95 cw(c73.25,123.95) 73.25,123.9
no net on Bottom Overlay "BOTTOMOVERLAY297" (solid, pour order 0): 101.9,136.55 cw(c101.95,136.55) 101.95,136.6 104.05,136.6 cw(c104.05,136.55) 104.1,136.55 104.1,132.45 cw(c104.05,132.45) 104.05,132.4 101.95,132.4 cw(c101.95,132.45) 101.9,132.45
no net on Bottom Overlay "BOTTOMOVERLAY298" (solid, pour order 0): 101.9,153.75 cw(c101.95,153.75) 101.95,153.8 104.05,153.8 cw(c104.05,153.75) 104.1,153.75 104.1,149.65 cw(c104.05,149.65) 104.05,149.6 101.95,149.6 cw(c101.95,149.65) 101.9,149.65
no net on Bottom Overlay "BOTTOMOVERLAY299" (solid, pour order 0): 51.95,123.9 cw(c51.95,123.95) 51.9,123.95 51.9,126.05 cw(c51.95,126.05) 51.95,126.1 56.05,126.1 cw(c56.05,126.05) 56.1,126.05 56.1,123.95 cw(c56.05,123.95) 56.05,123.9
no net on Top Overlay "TOPOVERLAY242" (solid, pour order 0): 27.082,135.994 27.506,136.418 27.718,135.782
no net on Top Overlay "TOPOVERLAY243" (solid, pour order 0): 33.882,135.894 34.306,136.318 34.518,135.682
no net on Top Overlay "TOPOVERLAY244" (solid, pour order 0): 35.8,140.5 34.8,140.5 35.3,141.5
no net on Top Overlay "TOPOVERLAY245" (solid, pour order 0): 106.53,21.33 106.177,20.27 105.47,20.977
no net on Top Overlay "TOPOVERLAY246" (solid, pour order 0): 114.4,111.7 112.4,111.7 112.4,115.2 114.4,115.2
no net on Top Overlay "TOPOVERLAY247" (solid, pour order 0): 110.439,115.75 111.5,116.811 112.03,115.22
no net on Top Overlay "TOPOVERLAY248" (solid, pour order 0): 129.689,115.75 130.75,116.811 131.28,115.22
no net on Top Overlay "TOPOVERLAY249" (solid, pour order 0): 131.6,113.55 133.6,113.55 133.6,110.05 131.6,110.05
no net on Top Overlay "TOPOVERLAY250" (solid, pour order 0): 118.45,112.85 118.45,114.85 121.95,114.85 121.95,112.85
no net on Top Overlay "TOPOVERLAY251" (solid, pour order 0): 122,110.875 120.5,110.875 121.25,112.375
no net on Top Overlay "TOPOVERLAY252" (solid, pour order 0): 141.5,110.875 140,110.875 140.75,112.375
no net on Top Overlay "TOPOVERLAY253" (solid, pour order 0): 139.8,114.9 139.8,112.9 136.3,112.9 136.3,114.9
no net on Top Overlay "TOPOVERLAY300" (solid, pour order 0): 45 vertices, not listed, extent 236.45,34.942 239.739,38.536
no net on Top Overlay "TOPOVERLAY301" (solid, pour order 0): 62 vertices, not listed, extent 249.812,35.005 252.805,38.479
no net on Top Overlay "TOPOVERLAY302" (solid, pour order 0): 36 vertices, not listed, extent 253.083,35 256.602,38.48
GND_A on TOP "TOP179" (solid, pour order 236): 109 vertices, not listed, extent 21,41.4 70.317,164
GND_A on TOP "TOP182" (solid, pour order 239): 56 vertices, not listed, extent 50.05,41.45 63.45,49.05
IDCP on TOP "TOP1" (solid, pour order 58): 99.1,107.4 cw(c99.1,107.9) 98.6,107.9 98.6,112.6 cw(c99.1,112.6) 99.1,113.1 105.1,113.1 cw(c105.1,112.6) 105.6,112.6 105.6,107.9 cw(c105.1,107.9) 105.1,107.4
SIGN00979 on TOP "TOP2" (solid, pour order 59): 67.75,94.7 cw(c67.75,94.85) 67.6,94.85 67.6,97.25 cw(c67.75,97.25) 67.75,97.4 70.75,97.4 cw(c70.75,97.25) 70.9,97.25 70.9,94.85 cw(c70.75,94.85) 70.75,94.7
SIGN00980 on TOP "TOP3" (solid, pour order 60): 67.75,86.8 cw(c67.75,86.95) 67.6,86.95 67.6,89.05 cw(c67.75,89.05) 67.75,89.2 70.75,89.2 cw(c70.75,89.05) 70.9,89.05 70.9,86.95 cw(c70.75,86.95) 70.75,86.8
SIGN00981 on TOP "TOP4" (solid, pour order 61): 67.75,78.6 cw(c67.75,78.75) 67.6,78.75 67.6,81.25 cw(c67.75,81.25) 67.75,81.4 70.75,81.4 cw(c70.75,81.25) 70.9,81.25 70.9,78.75 cw(c70.75,78.75) 70.75,78.6
IDCP on TOP "TOP5" (solid, pour order 62): 161.1,107.4 cw(c161.1,107.9) 160.6,107.9 160.6,112.6 cw(c161.1,112.6) 161.1,113.1 167.1,113.1 cw(c167.1,112.6) 167.6,112.6 167.6,107.9 cw(c167.1,107.9) 167.1,107.4
IDCP on TOP "TOP6" (solid, pour order 63): 223.1,107.4 cw(c223.1,107.9) 222.6,107.9 222.6,112.6 cw(c223.1,112.6) 223.1,113.1 229.1,113.1 cw(c229.1,112.6) 229.6,112.6 229.6,107.9 cw(c229.1,107.9) 229.1,107.4
GND_F on TOP "TOP7" (solid, pour order 64): 267.03,86 cw(c267.03,86.15) 266.885,86.111 ccw(c263.6,85.234) 264.243,88.572 cw(c265,92.5) 264.243,96.428 ccw(c263.6,99.766) 267,99.766 267,99.85 cw(c267.15,99.85) 267.15,100 268.85,100 cw(c268.85,99.85) 269,99.85 269,86.15 cw(c268.85,86.15) 268.85,86
GND_F on TOP "TOP8" (solid, pour order 65): 254.35,21 cw(c254.35,21.15) 254.2,21.15 254.2,22.85 cw(c254.35,22.85) 254.35,23 257.734,23 ccw(c257.734,26.4) 261.072,25.757 cw(c265,25) 264.243,28.928 ccw(c263.6,32.266) 267,32.266 267,33.55 cw(c267.15,33.55) 267.15,33.7 268.85,33.7 cw(c268.85,33.55) 269,33.55 269,21.15 cw(c268.85,21.15) 268.85,21
GND_F on TOP "TOP9" (solid, pour order 66): 145,21 cw(c145,25) 148.928,25.757 ccw(c152.266,26.4) 152.266,23 157.35,23 cw(c157.35,22.85) 157.5,22.85 157.5,21.15 cw(c157.35,21.15) 157.35,21
SIGN00983 on TOP "TOP10" (solid, pour order 67): 68.85,102.4 cw(c68.85,102.55) 68.7,102.55 68.7,105.95 cw(c68.85,105.95) 68.85,106.1 69.75,106.1 cw(c69.75,105.95) 69.9,105.95 69.9,102.55 cw(c69.75,102.55) 69.75,102.4
GND_V on TOP "TOP11" (solid, pour order 68): 154.146,72.646 cw(c154.5,73) 154.5,73.5 156.5,73.5 cw(c156.5,73) 156.854,72.646 155.854,71.646 cw(c155.5,72) 155.146,71.646
GND_A on TOP "TOP22" (solid, pour order 79): 75.4,51.35 cw(c75.4,51.5) 75.25,51.5 75.25,52 cw(c75.4,52) 75.4,52.15 75.75,52.15 76.556,52.956 cw(c76.662,52.85) 76.662,53 79.35,53 cw(c79.35,52.85) 79.5,52.85 79.5,52.15 cw(c79.35,52.15) 79.35,52 76.95,52 76.344,51.394 cw(c76.238,51.5) 76.238,51.35
GND_A on TOP "TOP23" (solid, pour order 80): 87.35,49.95 cw(c87.35,50.1) 87.2,50.1 87.2,51.9 cw(c87.35,51.9) 87.35,52.05 87.8,52.05 cw(c87.8,51.9) 87.95,51.9 87.95,50.1 cw(c87.8,50.1) 87.8,49.95
GND_A on TOP "TOP24" (solid, pour order 81): 69.85,49.55 cw(c69.85,49.7) 69.7,49.7 69.7,51.75 cw(c69.85,51.75) 69.85,51.9 70.3,51.9 cw(c70.3,51.75) 70.45,51.75 70.45,50.5 cw(c70.3,50.5) 70.39,50.38 ccw(c70.6,50.1) 70.25,50.1 70.25,49.7 cw(c70.1,49.7) 70.1,49.55
GND_D on TOP "TOP25" (solid, pour order 82): 110.85,31.65 cw(c110.85,31.8) 110.7,31.8 110.7,32.2 cw(c110.85,32.2) 110.85,32.35 111.8,32.35 cw(c111.8,32.2) 111.95,32.2 111.95,31.8 cw(c111.8,31.8) 111.8,31.65
GND_D on TOP "TOP26" (solid, pour order 83): 110.75,30.15 cw(c110.75,30.3) 110.6,30.3 110.6,30.7 cw(c110.75,30.7) 110.75,30.85 111.9,30.85 cw(c111.9,30.7) 112.05,30.7 112.05,30.3 cw(c111.9,30.3) 111.9,30.15
GND_A on TOP "TOP27" (solid, pour order 84): 21 vertices, not listed, extent 92.85,47.15 94.35,50.95
GND_A on TOP "TOP28" (solid, pour order 85): 21 vertices, not listed, extent 92.105,48.4 94.6,53.1
GND_A on TOP "TOP29" (solid, pour order 86): 149.35,49.95 cw(c149.35,50.1) 149.2,50.1 149.2,52 cw(c149.35,52) 149.35,52.15 149.8,52.15 cw(c149.8,52) 149.95,52 149.95,50.1 cw(c149.8,50.1) 149.8,49.95
GND_A on TOP "TOP30" (solid, pour order 87): 21 vertices, not listed, extent 154.85,47 156.3,51.35
GND_A on TOP "TOP31" (solid, pour order 88): 21 vertices, not listed, extent 154.105,48.4 156.6,53.1
GND_D on TOP "TOP32" (solid, pour order 89): 174.4,32.9 cw(c174.4,33.05) 174.25,33.05 174.25,33.8 cw(c174.4,33.8) 174.4,33.95 175.25,33.95 175.25,34.95 cw(c175.4,34.95) 175.4,35.1 175.8,35.1 cw(c175.8,34.95) 175.95,34.95 175.95,33.05 cw(c175.8,33.05) 175.8,32.9
GND_D on TOP "TOP33" (solid, pour order 90): 175.65,35.7 cw(c175.65,35.85) 175.5,35.85 175.5,36.15 cw(c175.65,36.15) 175.65,36.3 176.882,36.3 cw(c176.882,36.15) 176.947,36.285 ccw(c177.1,36.6) 177.1,36.25 177.75,36.25 cw(c177.75,36.1) 177.9,36.1 177.9,35.9 cw(c177.75,35.9) 177.75,35.75 177.1,35.75 ccw(c177.1,35.4) 176.947,35.715 cw(c176.882,35.85) 176.882,35.7
GND_D on TOP "TOP34" (solid, pour order 91): 181.4,35.55 cw(c181.4,35.7) 181.25,35.7 181.25,36 cw(c181.4,36) 181.4,36.15 182.65,36.15 cw(c182.65,36) 182.8,36 182.8,35.7 cw(c182.65,35.7) 182.65,35.55
GND_D on TOP "TOP35" (solid, pour order 92): 181.2,34.15 cw(c181.2,34.3) 181.05,34.3 181.05,35.65 cw(c181.2,35.65) 181.2,35.8 181.7,35.8 cw(c181.7,35.65) 181.85,35.65 181.85,34.3 cw(c181.7,34.3) 181.7,34.15
GND_A on TOP "TOP36" (solid, pour order 93): 186.7,34.55 cw(c186.7,34.7) 186.55,34.7 186.55,35.85 cw(c186.7,35.85) 186.7,36 187.2,36 cw(c187.2,35.85) 187.35,35.85 187.35,34.7 cw(c187.2,34.7) 187.2,34.55
GND_A on TOP "TOP37" (solid, pour order 94): 186.85,34.35 cw(c186.85,34.5) 186.7,34.5 186.7,34.9 cw(c186.85,34.9) 186.85,35.05 187.95,35.05 cw(c187.95,34.9) 188.1,34.9 188.1,34.5 cw(c187.95,34.5) 187.95,34.35
GND_A on TOP "TOP38" (solid, pour order 95): 185.9,42.35 cw(c185.9,42.5) 185.75,42.5 185.75,42.9 cw(c185.9,42.9) 185.9,43.05 187.85,43.05 cw(c187.85,42.9) 188,42.9 188,42.5 cw(c187.85,42.5) 187.85,42.35
GND_A on TOP "TOP39" (solid, pour order 96): 186.8,42.4 cw(c186.8,42.55) 186.65,42.55 186.65,43.7 cw(c186.8,43.7) 186.8,43.85 187.2,43.85 cw(c187.2,43.7) 187.35,43.7 187.35,42.55 cw(c187.2,42.55) 187.2,42.4
GND_A on TOP "TOP40" (solid, pour order 97): 211.35,49.95 cw(c211.35,50.1) 211.2,50.1 211.2,52.15 cw(c211.35,52.15) 211.35,52.3 211.8,52.3 cw(c211.8,52.15) 211.95,52.15 211.95,50.1 cw(c211.8,50.1) 211.8,49.95
GND_A on TOP "TOP41" (solid, pour order 98): 21 vertices, not listed, extent 216.85,47.15 218.4,51
GND_A on TOP "TOP42" (solid, pour order 99): 20 vertices, not listed, extent 216.105,48.4 218.6,53.1
SIGN009139 on TOP "TOP43" (solid, pour order 100): 47.19,36.371 cw(c47.237,36.513) 47.18,36.374 46.668,36.586 cw(c46.725,36.725) 46.658,36.591 cw(c46.725,36.725) 46.619,36.831 46.919,37.131 cw(c47.025,37.025) 46.958,37.159 cw(c47.025,37.025) 47.159,37.092 cw(c47.025,37.025) 47.164,37.082 47.376,36.57 cw(c47.237,36.513) 47.379,36.56 cw(c47.237,36.513) 47.19,36.371
GND_A on TOP "TOP44" (solid, pour order 101): 50.2,40.35 cw(c50.2,40.5) 50.05,40.5 50.05,40.85 cw(c50.2,40.85) 50.2,41 52.95,41 cw(c52.95,40.85) 53.1,40.85 53.1,40.5 cw(c52.95,40.5) 52.95,40.35
GND_A on TOP "TOP45" (solid, pour order 102): 50.2,40.45 cw(c50.2,40.6) 50.05,40.6 50.05,41.55 cw(c50.2,41.55) 50.2,41.7 50.7,41.7 cw(c50.7,41.55) 50.85,41.55 50.85,40.6 cw(c50.7,40.6) 50.7,40.45
GND_A on TOP "TOP46" (solid, pour order 103): 51.75,40.45 cw(c51.75,40.6) 51.6,40.6 51.6,42.15 cw(c51.75,42.15) 51.75,42.3 52.2,42.3 cw(c52.2,42.15) 52.35,42.15 52.35,40.6 cw(c52.2,40.6) 52.2,40.45
GND_A on TOP "TOP47" (solid, pour order 104): 65.3,40.35 cw(c65.3,40.5) 65.15,40.5 65.15,40.85 cw(c65.3,40.85) 65.3,41 66.75,41 cw(c66.75,40.85) 66.9,40.85 66.9,40.5 cw(c66.75,40.5) 66.75,40.35
GND_A on TOP "TOP48" (solid, pour order 105): 65.2,40.4 cw(c65.2,40.55) 65.05,40.55 65.05,41.8 cw(c65.2,41.8) 65.2,41.95 65.65,41.95 cw(c65.65,41.8) 65.8,41.8 65.8,40.55 cw(c65.65,40.55) 65.65,40.4
GND_A on TOP "TOP49" (solid, pour order 106): 55.2,40.05 cw(c55.2,40.2) 55.05,40.2 55.05,40.8 cw(c55.2,40.8) 55.2,40.95 56.3,40.95 56.356,41.006 cw(c56.462,40.9) 56.462,41.05 58.3,41.05 cw(c58.3,40.9) 58.45,40.9 58.45,40.5 cw(c58.3,40.5) 58.3,40.35 56.55,40.35 56.294,40.094 cw(c56.188,40.2) 56.188,40.05
GND_A on TOP "TOP50" (solid, pour order 107): 56.8,40.4 cw(c56.8,40.55) 56.65,40.55 56.65,41.65 cw(c56.8,41.65) 56.8,41.8 57.2,41.8 cw(c57.2,41.65) 57.35,41.65 57.35,40.55 cw(c57.2,40.55) 57.2,40.4
GND_D on TOP "TOP51" (solid, pour order 108): 83.15,24.9 cw(c83.15,25.05) 83,25.05 83,26.85 cw(c83.15,26.85) 83.15,27 83.5,27 cw(c83.5,26.85) 83.65,26.85 83.65,25.05 cw(c83.5,25.05) 83.5,24.9
GND_D on TOP "TOP52" (solid, pour order 109): 82.35,25.65 cw(c82.35,25.8) 82.2,25.8 82.2,26.25 cw(c82.35,26.25) 82.35,26.4 83.3,26.4 cw(c83.3,26.25) 83.45,26.25 83.45,25.8 cw(c83.3,25.8) 83.3,25.65
GND_D on TOP "TOP53" (solid, pour order 110): 81.25,26.8 cw(c81.25,26.95) 81.1,26.95 81.1,29.15 cw(c81.25,29.15) 81.25,29.3 81.85,29.3 cw(c81.85,29.15) 82,29.15 82,26.95 cw(c81.85,26.95) 81.85,26.8
GND_D on TOP "TOP54" (solid, pour order 111): 80.4,27.55 cw(c80.4,27.7) 80.25,27.7 80.25,28.35 cw(c80.4,28.35) 80.4,28.5 81.65,28.5 cw(c81.65,28.35) 81.8,28.35 81.8,27.7 cw(c81.65,27.7) 81.65,27.55
GND_D on TOP "TOP55" (solid, pour order 112): 83.2,29.05 cw(c83.2,29.2) 83.05,29.2 83.05,30.3 cw(c83.2,30.3) 83.2,30.45 83.8,30.45 cw(c83.8,30.3) 83.95,30.3 83.95,29.2 cw(c83.8,29.2) 83.8,29.05
GND_D on TOP "TOP56" (solid, pour order 113): 23 vertices, not listed, extent 82.7,32.7 85.15,36.85
GND_D on TOP "TOP57" (solid, pour order 114): 87.5,25.2 cw(c87.5,25.35) 87.35,25.35 87.35,26.55 cw(c87.5,26.55) 87.5,26.7 87.85,26.7 cw(c87.85,26.55) 88,26.55 88,25.35 cw(c87.85,25.35) 87.85,25.2
GND_D on TOP "TOP58" (solid, pour order 115): 87.85,25.05 cw(c87.85,25.2) 87.7,25.2 87.7,25.7 cw(c87.85,25.7) 87.85,25.85 88.75,25.85 cw(c88.75,25.7) 88.9,25.7 88.9,25.2 cw(c88.75,25.2) 88.75,25.05
GND_D on TOP "TOP59" (solid, pour order 116): 106.05,31.5 cw(c106.05,31.65) 105.9,31.65 105.9,32 cw(c106.05,32) 106.05,32.15 109.65,32.15 cw(c109.65,32) 109.8,32 109.8,31.65 cw(c109.65,31.65) 109.65,31.5
GND_D on TOP "TOP60" (solid, pour order 117): 106.75,30.2 cw(c106.75,30.35) 106.6,30.35 106.6,31.8 cw(c106.75,31.8) 106.75,31.95 107.2,31.95 cw(c107.2,31.8) 107.35,31.8 107.35,30.35 cw(c107.2,30.35) 107.2,30.2
GND_D on TOP "TOP61" (solid, pour order 118): 111.55,29.1 cw(c111.55,29.25) 111.4,29.25 111.4,32.95 cw(c111.55,32.95) 111.55,33.1 112,33.1 cw(c112,32.95) 112.15,32.95 112.15,29.25 cw(c112,29.25) 112,29.1
GND_D on TOP "TOP62" (solid, pour order 119): 111.2,35.75 cw(c111.2,35.9) 111.05,35.9 111.05,37.15 cw(c111.2,37.15) 111.2,37.3 111.5,37.3 cw(c111.5,37.15) 111.65,37.15 111.65,35.9 cw(c111.5,35.9) 111.5,35.75
GND_D on TOP "TOP63" (solid, pour order 120): 35 vertices, not listed, extent 171.65,31.95 176.75,37.2
GND_D on TOP "TOP64" (solid, pour order 121): 174.05,42.55 cw(c174.05,42.7) 173.9,42.7 173.9,43.35 cw(c174.05,43.35) 174.05,43.5 177.85,43.5 cw(c177.85,43.35) 178,43.35 178,42.7 cw(c177.85,42.7) 177.85,42.55
GND_D on TOP "TOP65" (solid, pour order 122): 168.65,41.05 cw(c168.65,41.2) 168.5,41.2 168.5,41.65 cw(c168.65,41.65) 168.65,41.8 170,41.8 cw(c170,41.65) 170.15,41.65 170.15,41.2 cw(c170,41.2) 170,41.05
GND_D on TOP "TOP66" (solid, pour order 123): 169.6,41.1 cw(c169.6,41.25) 169.45,41.25 169.45,42.7 cw(c169.6,42.7) 169.6,42.85 170,42.85 cw(c170,42.7) 170.15,42.7 170.15,41.25 cw(c170,41.25) 170,41.1
GND_D on TOP "TOP67" (solid, pour order 124): 167.5,35 cw(c167.5,35.15) 167.35,35.15 167.35,35.5 cw(c167.5,35.5) 167.5,35.65 168.65,35.65 cw(c168.65,35.5) 168.8,35.5 168.8,35.15 cw(c168.65,35.15) 168.65,35
GND_D on TOP "TOP68" (solid, pour order 125): 168.4,34.2 cw(c168.4,34.35) 168.25,34.35 168.25,35.25 cw(c168.4,35.25) 168.4,35.4 168.8,35.4 cw(c168.8,35.25) 168.95,35.25 168.95,34.35 cw(c168.8,34.35) 168.8,34.2
GND_D on TOP "TOP69" (solid, pour order 126): 24 vertices, not listed, extent 176.9,40.45 184.75,43.8
GND_A on TOP "TOP70" (solid, pour order 127): 202,42.05 cw(c202,42.2) 201.85,42.2 201.85,43.95 cw(c202,43.95) 202,44.1 202.3,44.1 cw(c202.3,43.95) 202.45,43.95 202.45,42.2 cw(c202.3,42.2) 202.3,42.05
GND_A on TOP "TOP71" (solid, pour order 128): 202.25,42.65 cw(c202.25,42.8) 202.1,42.8 202.1,43.2 cw(c202.25,43.2) 202.25,43.35 203.55,43.35 cw(c203.55,43.2) 203.7,43.2 203.7,42.8 cw(c203.55,42.8) 203.55,42.65
GND_A on TOP "TOP72" (solid, pour order 129): 35 vertices, not listed, extent 201.3,37.775 204.75,43.425
VREF_2.5V on TOP "TOP73" (solid, pour order 130): 200.625,37.825 cw(c200.625,37.975) 200.589,37.829 cw(c200.625,37.975) 200.519,38.081 200.694,38.256 cw(c200.8,38.15) 200.906,38.256 201.081,38.081 cw(c200.975,37.975) 201.109,38.042 cw(c200.975,37.975) 200.975,37.825
GND_A on TOP "TOP74" (solid, pour order 131): 202.15,34.2 cw(c202.15,34.35) 202,34.35 202,34.8 cw(c202.15,34.8) 202.15,34.95 203.6,34.95 cw(c203.6,34.8) 203.75,34.8 203.75,34.35 cw(c203.6,34.35) 203.6,34.2
GND_A on TOP "TOP75" (solid, pour order 132): 202,32.65 cw(c202,32.8) 201.85,32.8 201.85,34.5 cw(c202,34.5) 202,34.65 202.35,34.65 cw(c202.35,34.5) 202.5,34.5 202.5,32.8 cw(c202.35,32.8) 202.35,32.65
VDD5_D on TOP "TOP76" (solid, pour order 133): 112.386,37.133 cw(c112.75,37.3) 113.033,37.583 113.333,37.283 cw(c113.05,37) 113.112,36.605 112.773,36.552 cw(c112.75,36.7) 112.614,36.638
GND_A on TOP "TOP79" (solid, pour order 136): 52.858,40.05 cw(c52.858,40.2) 52.721,40.26 ccw(c52.4,40.4) 52.75,40.4 52.75,40.85 cw(c52.9,40.85) 52.9,41 52.988,41 cw(c52.988,40.85) 53.094,40.956 53.1,40.95 56.1,40.95 cw(c56.1,40.8) 56.25,40.8 56.25,40.2 cw(c56.1,40.2) 56.1,40.05
GND_D on TOP "TOP80" (solid, pour order 137): 106.7,29.65 cw(c106.7,29.8) 106.55,29.8 106.55,30.7 cw(c106.7,30.7) 106.7,30.85 108.15,30.85 108.15,31.9 cw(c108.3,31.9) 108.3,32.05 108.7,32.05 cw(c108.7,31.9) 108.85,31.9 108.85,30.75 110.05,30.75 cw(c110.05,30.6) 110.2,30.6 110.2,29.8 cw(c110.05,29.8) 110.05,29.65
GND_V on TOP "TOP83" (solid, pour order 140): 55 vertices, not listed, extent 100,135 109.2,140.5
SIGN00616 on TOP "TOP84" (solid, pour order 141): 101.4,141.55 cw(c101.4,141.7) 101.25,141.7 101.25,142.2 cw(c101.4,142.2) 101.4,142.35 102.35,142.35 cw(c102.35,142.2) 102.5,142.2 102.5,141.7 cw(c102.35,141.7) 102.35,141.55
SIGN00616 on TOP "TOP85" (solid, pour order 142): 100.05,139.5 cw(c100.05,139.65) 99.9,139.65 99.9,142.2 cw(c100.05,142.2) 100.05,142.35 101.675,142.35 cw(c101.675,142.2) 101.825,142.2 101.825,141.387 cw(c101.675,141.387) 101.781,141.281 101.1,140.6 101.1,139.65 cw(c100.95,139.65) 100.95,139.5
VP_5V_V on TOP "TOP86" (solid, pour order 143): 103.7,141.55 cw(c103.7,141.7) 103.55,141.7 103.55,142.2 cw(c103.7,142.2) 103.7,142.35 105.4,142.35 cw(c105.4,142.2) 105.55,142.2 105.55,141.7 cw(c105.4,141.7) 105.4,141.55
GND_B on TOP "TOP87" (solid, pour order 144): 55 vertices, not listed, extent 54.5,118.8 60,128
SIGN0074 on TOP "TOP88" (solid, pour order 145): 59,127.95 cw(c59.15,127.95) 59.15,128.1 61.7,128.1 cw(c61.7,127.95) 61.85,127.95 61.85,126.325 cw(c61.7,126.325) 61.7,126.175 60.887,126.175 cw(c60.887,126.325) 60.781,126.219 60.1,126.9 59.15,126.9 cw(c59.15,127.05) 59,127.05
SIGN0074 on TOP "TOP89" (solid, pour order 146): 61.05,126.6 cw(c61.2,126.6) 61.2,126.75 61.7,126.75 cw(c61.7,126.6) 61.85,126.6 61.85,125.65 cw(c61.7,125.65) 61.7,125.5 61.2,125.5 cw(c61.2,125.65) 61.05,125.65
VP_5V_B on TOP "TOP90" (solid, pour order 147): 61.05,124.3 cw(c61.2,124.3) 61.2,124.45 61.7,124.45 cw(c61.7,124.3) 61.85,124.3 61.85,122.6 cw(c61.7,122.6) 61.7,122.45 61.2,122.45 cw(c61.2,122.6) 61.05,122.6
GND_A on TOP "TOP100" (solid, pour order 157): 132.762,23.4 cw(c132.762,23.55) 132.656,23.444 132.4,23.7 131.962,23.7 cw(c131.962,23.85) 131.856,23.956 131.857,23.957 132.4,24.5 132.4,26.85 cw(c132.55,26.85) 132.55,27 134.05,27 cw(c134.05,26.85) 134.2,26.85 134.2,23.55 cw(c134.05,23.55) 134.05,23.4
GND_D on TOP "TOP101" (solid, pour order 158): 21 vertices, not listed, extent 111.35,22.4 116.9,29.75
GND_D on TOP "TOP102" (solid, pour order 159): 21 vertices, not listed, extent 105.7,21.8 107.8,27.25
GND_D on TOP "TOP103" (solid, pour order 160): 17 vertices, not listed, extent 105.8,21 107.8,22.6
GND_D on TOP "TOP104" (solid, pour order 161): 106.35,25 cw(c106.35,25.15) 106.2,25.15 106.2,25.85 cw(c106.35,25.85) 106.35,26 107.55,26 cw(c107.55,25.85) 107.7,25.85 107.7,25.15 cw(c107.55,25.15) 107.55,25
GND_D on TOP "TOP105" (solid, pour order 162): 106.35,22 cw(c106.35,22.15) 106.2,22.15 106.2,22.85 cw(c106.35,22.85) 106.35,23 107.55,23 cw(c107.55,22.85) 107.7,22.85 107.7,22.15 cw(c107.55,22.15) 107.55,22
IWN on TOP "TOP112" (solid, pour order 169): 237.25,163.45 cw(c237.4,163.45) 237.4,163.6 238.931,163.6 cw(c238.931,163.45) 238.964,163.304 ccw(c239.375,161.5) 237.548,161.791 cw(c237.4,161.815) 237.25,161.815
IWN on TOP "TOP113" (solid, pour order 170): 248.452,161.791 ccw(c246.625,161.5) 247.036,163.304 cw(c247.069,163.45) 247.069,163.6 248.6,163.6 cw(c248.6,163.45) 248.75,163.45 248.75,161.815 cw(c248.6,161.815) 248.452,161.791
GND_W on TOP "TOP114" (solid, pour order 171): 216.146,72.646 cw(c216.5,73) 216.5,73.5 218.5,73.5 cw(c218.5,73) 218.854,72.646 217.854,71.646 cw(c217.5,72) 217.146,71.646
GND_U on TOP "TOP115" (solid, pour order 172): 92.146,72.646 cw(c92.5,73) 92.5,73.5 94.5,73.5 cw(c94.5,73) 94.854,72.646 93.854,71.646 cw(c93.5,72) 93.146,71.646
GND_W on TOP "TOP116" (solid, pour order 173): 55 vertices, not listed, extent 100,152.2 109.2,157.7
SIGN00715 on TOP "TOP117" (solid, pour order 174): 101.4,158.75 cw(c101.4,158.9) 101.25,158.9 101.25,159.4 cw(c101.4,159.4) 101.4,159.55 102.35,159.55 cw(c102.35,159.4) 102.5,159.4 102.5,158.9 cw(c102.35,158.9) 102.35,158.75
SIGN00715 on TOP "TOP118" (solid, pour order 175): 100.05,156.7 cw(c100.05,156.85) 99.9,156.85 99.9,159.4 cw(c100.05,159.4) 100.05,159.55 101.675,159.55 cw(c101.675,159.4) 101.825,159.4 101.825,158.587 cw(c101.675,158.587) 101.781,158.481 101.1,157.8 101.1,156.85 cw(c100.95,156.85) 100.95,156.7
VP_5V_W on TOP "TOP119" (solid, pour order 176): 103.7,158.75 cw(c103.7,158.9) 103.55,158.9 103.55,159.4 cw(c103.7,159.4) 103.7,159.55 105.4,159.55 cw(c105.4,159.4) 105.55,159.4 105.55,158.9 cw(c105.4,158.9) 105.4,158.75
GND_U on TOP "TOP120" (solid, pour order 177): 55 vertices, not listed, extent 71.7,118.8 77.2,128
SIGN0063 on TOP "TOP121" (solid, pour order 178): 76.2,127.95 cw(c76.35,127.95) 76.35,128.1 78.9,128.1 cw(c78.9,127.95) 79.05,127.95 79.05,126.325 cw(c78.9,126.325) 78.9,126.175 78.087,126.175 cw(c78.087,126.325) 77.981,126.219 77.3,126.9 76.35,126.9 cw(c76.35,127.05) 76.2,127.05
SIGN0063 on TOP "TOP122" (solid, pour order 179): 78.25,126.6 cw(c78.4,126.6) 78.4,126.75 78.9,126.75 cw(c78.9,126.6) 79.05,126.6 79.05,125.65 cw(c78.9,125.65) 78.9,125.5 78.4,125.5 cw(c78.4,125.65) 78.25,125.65
VP_5V_U on TOP "TOP123" (solid, pour order 180): 78.25,124.3 cw(c78.4,124.3) 78.4,124.45 78.9,124.45 cw(c78.9,124.3) 79.05,124.3 79.05,122.6 cw(c78.9,122.6) 78.9,122.45 78.4,122.45 cw(c78.4,122.6) 78.25,122.6
VP_DC on TOP "TOP124" (solid, pour order 181): 33 vertices, not listed, extent 100,85.9 163,128
VP_DC on TOP "TOP125" (solid, pour order 182): 27 vertices, not listed, extent 75.2,85.9 103,128
GND_D on TOP "TOP126" (solid, pour order 183): 111.05,40.8 cw(c111.05,40.95) 110.944,40.844 110.75,40.844 cw(c110.75,40.994) 110.6,40.994 110.6,41.85 cw(c110.75,41.85) 110.75,42 111.45,42 cw(c111.45,41.85) 111.6,41.85 111.6,41.5 112.75,41.5 cw(c112.75,41.35) 112.9,41.35 112.9,40.95 cw(c112.75,40.95) 112.75,40.8
GND_D on TOP "TOP127" (solid, pour order 184): 107.51,40.7 cw(c107.51,40.85) 107.367,40.897 ccw(c106.75,41.1) 107.4,41.1 107.4,42.35 cw(c107.55,42.35) 107.55,42.5 111.538,42.5 cw(c111.538,42.35) 111.644,42.456 111.906,42.194 cw(c111.8,42.088) 111.95,42.088 111.95,40.85 cw(c111.8,40.85) 111.8,40.7
GND_D on TOP "TOP128" (solid, pour order 185): 119.45,37.3 cw(c119.45,37.45) 119.3,37.45 119.3,39.15 cw(c119.45,39.15) 119.45,39.3 119.8,39.3 cw(c119.8,39.15) 119.95,39.15 119.95,37.45 cw(c119.8,37.45) 119.8,37.3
